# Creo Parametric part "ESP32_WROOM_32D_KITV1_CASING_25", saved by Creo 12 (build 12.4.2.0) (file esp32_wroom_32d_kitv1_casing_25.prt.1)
Units: Custom; MM, KILOGRAM, SECS

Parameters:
  PTC_WM_ITERATION = "0"
  PTC_WM_VERSION = "-.0"
  PTC_WM_LIFECYCLE_STATE = "In Work"
  PTC_WM_LIFECYCLE = "MO_CADDocument"
  PTC_WM_CREATED_BY = "Maximilian Roepper (Z0017RMS: MO)"
  PTC_WM_CREATED_ON = "18-Sep-26 11:36:42 AM"
  PTC_WM_MODIFIED_BY = "Maximilian Roepper (Z0017RMS: MO)"
  PTC_WM_MODIFIED_ON = "18-Sep-26 11:36:46 AM"
  PDMLINKNUMBER = "PDM000071455295"
  PTC_WM_NAME = "esp32_wroom_32d_kitv1_casing_25.prt"
  PTC_WM_NUMBER = "PDM000071455295"

Other parameters: WEIGHT, WEIGHT_FACTOR, WEIGHT_ADD, _MASS_TEMP, _DIFF_TEMP, MC_ERRORS, SUPPLIER

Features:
  1. coordinate system
  2. datum plane "PRT_YZ"
  3. datum plane "PRT_XY"
  4. datum plane "PRT_XZ"
  5. coordinate system
  6. datum axis
  7. datum axis
  8. datum axis
  9. coordinate system
  10. imported feature
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
Other named items: PRT, SIEMENS_MO, DRW_VIEW_ORG, PRT_X, PRT_Y, PRT_Z, CS0, ROUGH_GROB

Layers: 00_STD_CSYS-KSYS, 01_STD_PLANES-EBENEN, 02_STD_AXES-ACHSEN, 03_STD_CSYS-KSYS, 24_IMPORT_FEAT-IMPORT_KE

Surfaces: 5 plane, 1 cylinder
